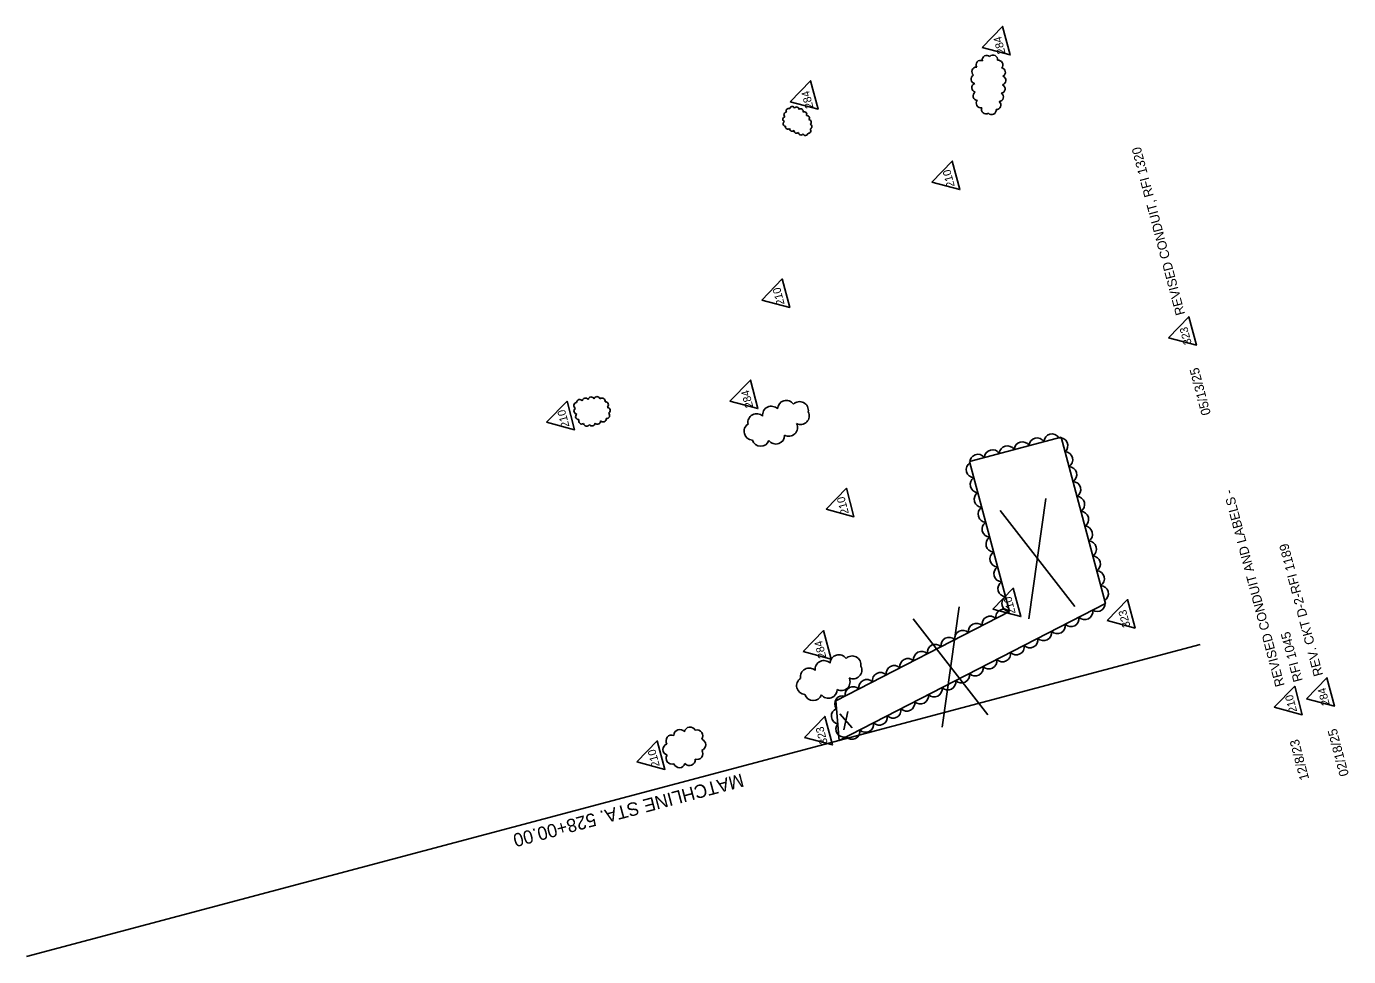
# Model space of a CAD drawing. Extents: x 930124 to 931186, y 628803 to 630086.
# Drawn here: x 930394 to 931186, y 628803 to 629360 of the extents above; entities that cross this region are included whole.
import ezdxf

# ---------------------------------------------------------------- set-up
doc = ezdxf.new("R2010")
doc.units = 0
for name, color, linetype in [('Cloud_dp', 7, 'Continuous'), ('MatchLines_dp', 7, 'Continuous'), ('NonPlottingEle_dp', 7, 'Continuous'), ('TextMinor', 7, 'Continuous')]:
    doc.layers.add(name, color=color, linetype=linetype)

msp = doc.modelspace()

# ---------------------------------------------------------------- linework, layer by layer
at = {"layer": 'Cloud_dp'}
for p, q in [((930994.85, 629005.14), (931005.04, 629077.31)), ((931022.3, 629012.43), (930977.6, 629070.01)), ((930942.76, 628940.16), (930952.96, 629012.34)), ((930970.21, 628947.46), (930925.51, 629005.04)), ((930883.96, 628938.51), (930886.22, 628949.46)), ((930888.79, 628939.79), (930881.39, 628948.17))]:
    msp.add_line(p, q, dxfattribs=at)
for points in [[(930966.84, 629347.6), (930983.6, 629343.14), (930979.07, 629360.19)], [(930851.74, 629315.02), (930868.49, 629310.55), (930863.96, 629327.61)], [(930936.68, 629266.85), (930953.44, 629262.39), (930948.9, 629279.45)], [(930834.69, 629196.2), (930851.44, 629191.74), (930846.91, 629208.8)], [(931078.45, 629173.57), (931095.2, 629169.11), (931090.67, 629186.17)], [(930815.64, 629135.59), (930832.39, 629131.13), (930827.86, 629148.18)], [(930705.73, 629122.9), (930722.49, 629118.44), (930717.95, 629135.5)], [(930873.21, 629070.79), (930889.97, 629066.32), (930885.43, 629083.38)], [(930973.23, 629010.87), (930989.98, 629006.4), (930985.45, 629023.46)], [(931041.72, 629004.03), (931058.48, 628999.56), (931053.94, 629016.62)], [(930859.46, 628985.41), (930876.22, 628980.95), (930871.68, 628998)], [(931141.9, 628952.04), (931158.66, 628947.58), (931154.12, 628964.64)], [(931161.19, 628957.17), (931177.94, 628952.71), (931173.41, 628969.76)], [(930860.25, 628933.99), (930877.01, 628929.53), (930872.47, 628946.59)], [(930759.86, 628919.33), (930776.62, 628914.86), (930772.08, 628931.92)]]:
    msp.add_lwpolyline(points, close=True, dxfattribs=at)
for centre, radius, start, end in [((930965.83, 629337.18), 2.69, 65.81449, 210.81449), ((930969.56, 629340.2), 2.69, 47.02622, 192.02622), ((930973.34, 629340.3), 2.69, 351.17918, 136.17918), ((930976.48, 629337.25), 2.69, 315.47406, 100.47406), ((930962.8, 629328.61), 2.69, 115.67642, 260.67642), ((930963.33, 629333.12), 2.69, 85.90866, 230.90866), ((930978.03, 629332.7), 2.69, 297.05766, 82.05766), ((930978.36, 629327.77), 2.69, 285.53496, 70.53496), ((930963.28, 629323.43), 2.69, 109.9098, 254.9098), ((930977.87, 629322.77), 2.69, 278.3399, 63.3399), ((930964.05, 629318.58), 2.69, 123.04285, 268.04285), ((930965.96, 629314.1), 2.69, 138.15829, 283.15829), ((930975.34, 629313.05), 2.69, 265.6604, 50.6604), ((930976.87, 629317.81), 2.69, 273.85274, 58.85274), ((930848.86, 629304.56), 1.51, 99.66415, 244.66415), ((930849.47, 629307.29), 1.51, 90.23348, 235.23348), ((930850.78, 629309.54), 1.51, 64.25659, 209.25659), ((930852.93, 629310.64), 1.51, 25.19628, 170.19628), ((930855.55, 629310.45), 1.51, 1.35126, 146.35126), ((930858.01, 629309.31), 1.51, 343.81258, 128.81258), ((930860.11, 629307.52), 1.51, 330.43389, 115.43389), ((930861.78, 629305.31), 1.51, 318.65228, 103.65228), ((930969.06, 629310.45), 2.69, 157.53748, 302.53748), ((930972.48, 629310.01), 2.69, 222.67057, 7.67057), ((930848.98, 629301.89), 1.51, 120.6446, 265.6446), ((930850.35, 629300.11), 1.51, 169.55406, 314.55406), ((930852.91, 629298.84), 1.51, 172.8068, 317.8068), ((930855.53, 629297.64), 1.51, 172.84611, 317.84611), ((930862.53, 629297.6), 1.51, 259.199, 44.199), ((930862.87, 629302.8), 1.51, 303.2417, 88.2417), ((930863.2, 629300.1), 1.51, 285.88168, 70.88168), ((930858.17, 629296.61), 1.51, 179.33238, 324.33238), ((930860.76, 629296.37), 1.51, 205.1875, 350.1875), ((930723.9, 629132.9), 1.87, 96.65996, 241.65996), ((930723.96, 629129.65), 1.87, 120.40329, 265.40329), ((930725.56, 629134.69), 1.87, 32.99519, 177.99519), ((930728.98, 629135.57), 1.87, 30.58908, 175.58908), ((930732.44, 629136.21), 1.87, 25.45378, 170.45378), ((930735.9, 629136.44), 1.87, 17.07381, 162.07381), ((930738.93, 629135.59), 1.87, 346.88986, 131.88986), ((930740.9, 629133.31), 1.87, 309.55427, 94.55427), ((930741.94, 629130), 1.87, 300.35633, 85.35633), ((930840.37, 629127.34), 5.21, 43.31257, 188.31257), ((930849.37, 629130.82), 5.21, 33.91184, 178.91184), ((930857.39, 629130.06), 5.21, 350.30948, 135.30948), ((930724.99, 629126.34), 1.87, 129.1717, 274.1717), ((930726.84, 629123.72), 1.87, 156.12895, 301.12895), ((930736.24, 629123.63), 1.87, 219.62405, 4.62405), ((930739.53, 629124.99), 1.87, 220.2265, 5.2265), ((930741.63, 629127.01), 1.87, 262.67969, 47.67969), ((930831.6, 629122.83), 5.21, 46.10802, 191.10802), ((930857.93, 629126.73), 5.21, 243.02408, 28.02408), ((930729.65, 629122.43), 1.87, 189.46548, 334.46548), ((930732.94, 629122.58), 1.87, 210.79964, 355.79964), ((930829.28, 629117.44), 5.21, 122.47753, 267.47753), ((930843.2, 629115.09), 5.21, 216.02366, 1.02366), ((930850.9, 629119.77), 5.21, 241.49045, 26.49045), ((931008.65, 629111.09), 4.84, 32.39045, 177.39045), ((930834.05, 629113.7), 5.21, 196.32715, 341.32715), ((930981.89, 629103.97), 4.84, 32.39045, 177.39045), ((930990.81, 629106.34), 4.84, 32.39045, 177.39045), ((930999.73, 629108.71), 4.84, 32.39045, 177.39045), ((931013.28, 629108.87), 4.84, 311.5678, 96.5678), ((930964.31, 629098.86), 4.84, 37.7621, 182.7621), ((930972.97, 629101.6), 4.84, 32.39045, 177.39045), ((931016.28, 629100.41), 4.84, 302.39045, 87.39045), ((930962.07, 629094.54), 4.84, 122.39045, 267.39045), ((931018.65, 629091.49), 4.84, 302.39045, 87.39045), ((930964.44, 629085.62), 4.84, 122.39045, 267.39045), ((931021.02, 629082.57), 4.84, 302.39045, 87.39045), ((930966.82, 629076.7), 4.84, 122.39045, 267.39045), ((931023.39, 629073.65), 4.84, 302.39045, 87.39045), ((930969.19, 629067.78), 4.84, 122.39045, 267.39045), ((931025.76, 629064.73), 4.84, 302.39045, 87.39045), ((930971.56, 629058.86), 4.84, 122.39045, 267.39045), ((931028.13, 629055.82), 4.84, 302.39045, 87.39045), ((930973.93, 629049.94), 4.84, 122.39045, 267.39045), ((931030.51, 629046.9), 4.84, 302.39045, 87.39045), ((930976.3, 629041.02), 4.84, 122.39045, 267.39045), ((930978.67, 629032.1), 4.84, 122.39045, 267.39045), ((931032.88, 629037.98), 4.84, 302.39045, 87.39045), ((931035.25, 629029.06), 4.84, 302.39045, 87.39045), ((930981.04, 629023.19), 4.84, 122.39045, 267.39045), ((931037.62, 629020.14), 4.84, 302.39045, 87.39045), ((930983.42, 629014.27), 4.84, 122.39045, 267.39045), ((931035.71, 629014.29), 4.84, 236.34527, 21.34527), ((930971.55, 629001.81), 4.84, 44.70727, 189.70727), ((930979.76, 629006.03), 4.84, 44.70727, 189.70727), ((931020.05, 629005.23), 4.84, 224.70727, 9.70727), ((931028.26, 629009.45), 4.84, 224.70727, 9.70727), ((930955.13, 628993.37), 4.84, 44.70727, 189.70727), ((930963.34, 628997.59), 4.84, 44.70727, 189.70727), ((931003.63, 628996.79), 4.84, 224.70727, 9.70727), ((931011.84, 629001.01), 4.84, 224.70727, 9.70727), ((930938.72, 628984.93), 4.84, 44.70727, 189.70727), ((930946.93, 628989.15), 4.84, 44.70727, 189.70727), ((930987.22, 628988.35), 4.84, 224.70727, 9.70727), ((930995.43, 628992.57), 4.84, 224.70727, 9.70727), ((930880.88, 628978.36), 5.21, 33.91184, 178.91184), ((930888.91, 628977.6), 5.21, 350.30948, 135.30948), ((930922.3, 628976.49), 4.84, 44.70727, 189.70727), ((930930.51, 628980.71), 4.84, 44.70727, 189.70727), ((930970.8, 628979.91), 4.84, 224.70727, 9.70727), ((930979.01, 628984.13), 4.84, 224.70727, 9.70727), ((930863.11, 628970.37), 5.21, 46.10802, 191.10802), ((930871.88, 628974.88), 5.21, 43.31257, 188.31257), ((930889.44, 628974.28), 5.21, 243.02408, 28.02408), ((930905.89, 628968.06), 4.84, 44.70727, 189.70727), ((930914.1, 628972.27), 4.84, 44.70727, 189.70727), ((930954.39, 628971.48), 4.84, 224.70727, 9.70727), ((930962.59, 628975.7), 4.84, 224.70727, 9.70727), ((930860.79, 628964.98), 5.21, 122.47753, 267.47753), ((930882.41, 628967.31), 5.21, 241.49045, 26.49045), ((930889.47, 628959.61), 4.84, 44.70727, 189.70727), ((930897.68, 628963.84), 4.84, 44.70727, 189.70727), ((930946.18, 628967.26), 4.84, 224.70727, 9.70727), ((930865.56, 628961.24), 5.21, 196.32715, 341.32715), ((930874.72, 628962.64), 5.21, 216.02366, 1.02366), ((930883.25, 628954.18), 4.84, 72.56126, 217.56126), ((930929.76, 628958.82), 4.84, 224.70727, 9.70727), ((930937.97, 628963.04), 4.84, 224.70727, 9.70727), ((930881.28, 628946.77), 4.84, 112.68814, 257.68814), ((930913.35, 628950.38), 4.84, 224.70727, 9.70727), ((930921.56, 628954.6), 4.84, 224.70727, 9.70727), ((930883.99, 628938.98), 4.84, 140.60983, 285.60983), ((930896.93, 628941.94), 4.84, 224.70727, 9.70727), ((930905.14, 628946.16), 4.84, 224.70727, 9.70727), ((930780.75, 628931.95), 3.47, 68.46599, 213.46599), ((930785.5, 628935.25), 3.47, 36.09124, 181.09124), ((930791.74, 628936.76), 3.47, 26.21778, 171.21778), ((930795.92, 628934.99), 3.47, 322.74245, 107.74245), ((930797.64, 628929.57), 3.47, 287.59727, 72.59727), ((930888.73, 628937.72), 4.84, 224.70727, 9.70727), ((930778.94, 628926.73), 3.47, 108.09552, 253.09552), ((930795.89, 628924.21), 3.47, 251.06604, 36.06604), ((930780.8, 628921.46), 3.47, 145.8684, 290.8684), ((930785.33, 628919.32), 3.47, 198.51028, 343.51028), ((930791.3, 628920.59), 3.47, 220.57779, 5.57779)]:
    msp.add_arc(centre, radius, start, end, dxfattribs=at)
at = {"layer": 'MatchLines_dp'}
msp.add_lwpolyline([(931097.53, 628989.72), (930741.83, 628895.14), (930393.92, 628802.63)], dxfattribs=at)
at = {"layer": 'NonPlottingEle_dp'}
for p, q in [((930959.26, 629099.46), (931014.15, 629114.06)), ((931014.15, 629114.06), (931040.7, 629014.21)), ((930983.2, 629009.43), (930959.26, 629099.46)), ((931040.7, 629014.21), (930881.14, 628932.19)), ((930878.99, 628955.86), (930983.2, 629009.43)), ((930881.14, 628932.19), (930878.99, 628955.86))]:
    msp.add_line(p, q, dxfattribs=at)

# ---------------------------------------------------------------- texts
at = {"layer": 'Cloud_dp'}
for s, p in [('284', (930980.81, 629344.25)), ('284', (930865.7, 629311.66)), ('210', (930950.4, 629264.44)), ('210', (930848.4, 629193.79)), ('323', (931092.44, 629170.11)), ('284', (930829.6, 629132.24)), ('210', (930719.45, 629120.49)), ('210', (930886.93, 629068.37)), ('210', (930986.94, 629008.45)), ('323', (931055.72, 629000.56)), ('284', (930873.43, 628982.06)), ('210', (931155.62, 628949.63)), ('284', (931175.15, 628953.82)), ('323', (930874.25, 628930.53)), ('210', (930773.58, 628916.91))]:
    msp.add_text(s, height=4.799, rotation=104.89046, dxfattribs=at).set_placement(p)
at = {"layer": 'MatchLines_dp'}
msp.add_text('MATCHLINE STA. 528+00.00', height=8, rotation=194.89045, dxfattribs=at).set_placement((930822.6, 628912.48))
at = {"layer": 'TextMinor'}
for s, p in [('REVISED CONDUIT, RFI 1320', (931088.45, 629187.88)), ('05/13/25', (931103.91, 629127.96)), ('REVISED CONDUIT AND LABELS - ', (931148.14, 628965.21)), ('REV. CKT D-2-RFI 1189', (931171.19, 628971.48)), ('RFI 1045', (931158.97, 628968.09)), ('12/8/23', (931162.84, 628909.17)), ('02/18/25', (931186.65, 628911.55))]:
    msp.add_text(s, height=5.6, rotation=104.89045, dxfattribs=at).set_placement(p)

doc.saveas('drawing.dxf')
